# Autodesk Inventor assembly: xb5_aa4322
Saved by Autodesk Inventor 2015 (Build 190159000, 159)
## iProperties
Created: 2018-05
Part Number: xb5_aa4322
Checked By: TraceParts S.A.
Catalog Web Link: www.traceparts.com
Document SubType Name: Assembly
Designer: TraceParts
Company: TraceParts S.A.
Author: TraceParts
REFERENCE: XB5 AA4322
DESIGN: Unité de commande et de signalisation Ø 22 Harmony XB5 plastique - Boutons-poussoirs à impulsion avec marquage à poussoir affleurant ou dépassant - Produit comp
SUPPLIER: Schneider Electric
TraceParts.PartNumber: 10-29052009-077436
TraceParts.PartTitle: Unité de commande et de signalisation Ø 22 Harmony XB5 plastique - Boutons-poussoirs à impulsion avec marquage à poussoir affleurant ou dépassant - Produit comp
TraceParts.InstanceId: 10-29052009-077436AQV5GBURGI0CAC8VEH9QC9O5A
TraceParts.PartStatus: Published
TraceParts.PartVersion: 1.1.5
TRACEPARTS: TRACEPARTS
TraceParts.PartLanguage: fr
TraceParts.ClassPath: SCHNEIDER_ELECTRIC:10-29052009-077436
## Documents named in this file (8)
- C:\TPO v2\SharedFS\Outgoing\xb5_aa4322.iam
- C:\TPO v2\SharedFS\Outgoing\xb5_aa4322_01.ipt
- C:\TPO v2\SharedFS\Outgoing\xb5_aa4322_02.ipt
- C:\TPO v2\SharedFS\Outgoing\xb5_aa4322_03.ipt
- C:\TPO v2\SharedFS\Outgoing\xb5_aa4322_04.ipt
- C:\TPO v2\SharedFS\Outgoing\xb5_aa4322_05.ipt
- C:\TPO v2\SharedFS\Outgoing\xb5_aa4322_06.ipt
- C:\TPO v2\SharedFS\Outgoing\xb5_aa4322_07.ipt
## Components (7 placed, 7 different names)
1. xb5_aa4322_01:1
2. xb5_aa4322_02:1
3. xb5_aa4322_03:1
4. xb5_aa4322_04:1
5. xb5_aa4322_05:1
6. xb5_aa4322_06:1
7. xb5_aa4322_07:1
